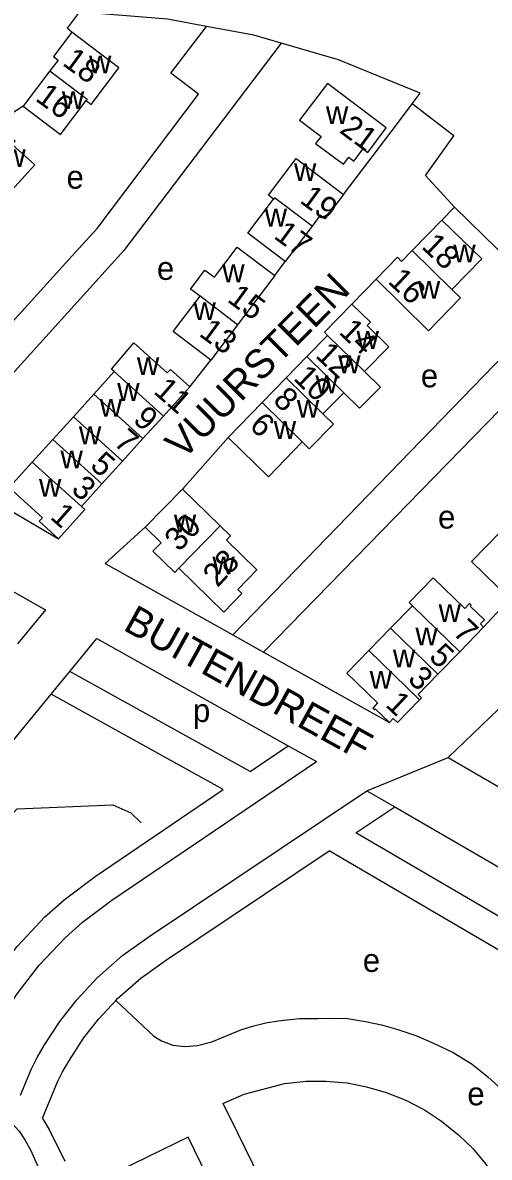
# Model space of a CAD drawing. Extents: x 159441 to 162086, y 388175 to 389787.
# Drawn here: x 161347.7 to 161428.2, y 389289.4 to 389484.9 of the extents above; entities that cross this region are included whole.
import ezdxf

# ---------------------------------------------------------------- set-up
doc = ezdxf.new("R2010")
doc.units = 0
for name, color, linetype in [('BLT_Basislijn', 7, 'Continuous'), ('BLT_Bebouwing', 7, 'Continuous'), ('BLT_Centroide', 7, 'Continuous'), ('BLT_Huisnummer', 7, 'Continuous'), ('BLT_Huisnummer_ tussenligend', 7, 'Continuous'), ('BLT_Onderverdeling_panden', 7, 'Continuous'), ('BLT_Straatnaam', 7, 'Continuous'), ('BLT_Vlakafsluiter', 7, 'Continuous')]:
    doc.layers.add(name, color=color, linetype=linetype)

msp = doc.modelspace()

# ---------------------------------------------------------------- linework, layer by layer
at = {"layer": 'BLT_Basislijn'}
for p, q in [((161356.15, 389483.29), (161355.35, 389483.98)), ((161347.75, 389470.52), (161343.08, 389467.5)), ((161402.99, 389455.31), (161412.3, 389467.53)), ((161422.15, 389453.11), (161417.14, 389458.59)), ((161420, 389450.91), (161422.15, 389453.11)), ((161391.14, 389441.35), (161392.97, 389443.77)), ((161408.63, 389440.71), (161404.43, 389436.41)), ((161383.9, 389379.42), (161439.23, 389436.44)), ((161376.48, 389422.13), (161380.11, 389426.78)), ((161383.09, 389413.41), (161375.23, 389404.54)), ((161368.81, 389397.97), (161361.91, 389391.73)), ((161361.91, 389391.73), (161383.9, 389379.42)), ((161427.19, 389380.73), (161431.71, 389385.62)), ((161421.08, 389358.27), (161444.06, 389380.35)), ((161352.59, 389369.18), (161355.81, 389373.11))]:
    msp.add_line(p, q, dxfattribs=at)
for points in [[(161357.39, 389486.75), (161355.35, 389483.98)], [(161379.36, 389484.27), (161372.66, 389485.51), (161361.32, 389486.43)], [(161334.35, 389420.66), (161357.32, 389445.96), (161360.5, 389449.47), (161378.02, 389472.57), (161373.23, 389476.2), (161379.36, 389484.27)], [(161392.24, 389481.39), (161387.52, 389482.77), (161379.36, 389484.27)], [(161392.24, 389481.39), (161365.12, 389445.63), (161331.26, 389408.25)], [(161414.87, 389470.94), (161416.25, 389472.77), (161402.15, 389478.49), (161392.24, 389481.39)], [(161412.3, 389467.53), (161414.87, 389470.94)], [(161417.14, 389458.59), (161422.02, 389465.43), (161414.87, 389470.94)], [(161439.23, 389436.44), (161422.15, 389453.11)], [(161389.22, 389376.43), (161443.62, 389432.16)], [(161297.62, 389404.04), (161302.19, 389409.6), (161338.34, 389391.17), (161351.6, 389383.74), (161346.77, 389377.86)], [(161331.26, 389408.25), (161344, 389401.76), (161353.86, 389395.98)], [(161383.9, 389379.42), (161389.22, 389376.43)], [(161355.81, 389373.11), (161360.47, 389378.78), (161393.45, 389360.31)], [(161389.22, 389376.43), (161404.55, 389367.85), (161410.92, 389364.29)], [(161386.93, 389355.89), (161355.81, 389373.11)], [(161319.95, 389308.88), (161320.68, 389311.3), (161331.61, 389342.43), (161333.68, 389346.28), (161339.03, 389352.68), (161352.59, 389369.18)], [(161382.28, 389352.75), (161352.59, 389369.18)], [(161386.93, 389355.89), (161393.45, 389360.31)], [(161393.45, 389360.31), (161398.33, 389357.58)], [(161339.24, 389303.76), (161339.4, 389304.13), (161341.55, 389308.92), (161343.9, 389313.22), (161346.73, 389317.54), (161350.53, 389322.46), (161354.99, 389327.2), (161357.99, 389329.87), (161363.07, 389333.69), (161398.33, 389357.58)], [(161421.08, 389358.27), (161443.36, 389345.36)], [(161332.9, 389303.9), (161333.46, 389304.11), (161334.01, 389304.57), (161334.43, 389305.24), (161334.83, 389306.15), (161337.06, 389311.14), (161339.61, 389315.79), (161342.66, 389320.44), (161346.72, 389325.7), (161351.5, 389330.79), (161354.82, 389333.74), (161360.16, 389337.76), (161382.28, 389352.75)], [(161347.32, 389300.09), (161349.17, 389304.61), (161350.19, 389306.55), (161351.46, 389308.73), (161354.07, 389312.79), (161357.02, 389316.52), (161360.52, 389320.29), (161364.92, 389324.19), (161369.65, 389327.54), (161407.03, 389352.54)], [(161407.03, 389352.54), (161411.85, 389349.75)], [(161334.61, 389338.55), (161344.95, 389344.94), (161345.64, 389347), (161345.67, 389348.4), (161346.72, 389349.45), (161363.24, 389350.1), (161366.31, 389348.76), (161368.09, 389347.03)], [(161405.15, 389345.27), (161411.85, 389349.75)], [(161411.85, 389349.75), (161451.41, 389326.83)], [(161437.49, 389326.37), (161405.15, 389345.27)], [(161363.72, 389316.39), (161364.02, 389316.71), (161368.03, 389320.26), (161372.49, 389323.42), (161400.53, 389342.18)], [(161429.8, 389325.08), (161400.53, 389342.18)], [(161351.09, 389296.09), (161353.71, 389302.5), (161354.56, 389304.12), (161355.73, 389306.11), (161358.14, 389309.88), (161360.82, 389313.26), (161363.72, 389316.39)], [(161363.72, 389316.39), (161370.27, 389310.24), (161371.59, 389309.47), (161373.58, 389308.7), (161375.63, 389308.47), (161377.84, 389308.61), (161380.29, 389309.26), (161382.95, 389310.38), (161385.33, 389311.31), (161387.33, 389311.97), (161389.59, 389312.53), (161391.76, 389312.88), (161395.4, 389313.27), (161398.59, 389313.32), (161401.53, 389313.34), (161403.73, 389313.27), (161406.83, 389312.75), (161409.54, 389312.22), (161412.4, 389311.42), (161415.51, 389310.35), (161418.51, 389309.04), (161421.91, 389307.43), (161425.21, 389305.43), (161427.9, 389303.23), (161430.39, 389300.98)], [(161345.46, 389295.54), (161345.74, 389295.3), (161347.05, 389293.86), (161348.06, 389292.39), (161349.03, 389290.66), (161350.35, 389287.69), (161352.98, 389282.25), (161359.9, 389268.04), (161368.55, 389250.2), (161369.85, 389247.56)], [(161351.09, 389296.09), (161351.22, 389295.91)], [(161351.22, 389295.91), (161352.25, 389294.17), (161354.92, 389288.69)], [(161382.75, 389279.37), (161376.24, 389292.82), (161357.36, 389283.67)]]:
    msp.add_lwpolyline(points, dxfattribs=at)
at = {"layer": 'BLT_Bebouwing'}
for p, q in [((161391.14, 389441.35), (161384.72, 389432.87)), ((161396.7, 389427.36), (161400.27, 389431.02)), ((161393.13, 389423.7), (161396.7, 389427.36)), ((161359.92, 389420.89), (161363.45, 389424.79)), ((161388.97, 389419.43), (161393.13, 389423.7)), ((161356.41, 389416.98), (161359.92, 389420.89)), ((161403.06, 389421.14), (161399.47, 389417.49)), ((161388.97, 389419.43), (161383.09, 389413.41)), ((161352.88, 389413.07), (161356.41, 389416.98)), ((161371.94, 389417.13), (161368.41, 389413.23)), ((161349.33, 389409.19), (161352.88, 389413.07)), ((161368.41, 389413.23), (161364.88, 389409.33)), ((161364.88, 389409.33), (161361.35, 389405.43)), ((161361.35, 389405.43), (161357.82, 389401.53))]:
    msp.add_line(p, q, dxfattribs=at)
for points in [[(161356.15, 389483.29), (161352.98, 389479.09), (161353.77, 389478.48), (161352.35, 389476.6)], [(161358.64, 389471.48), (161359.51, 389470.83), (161364.28, 389477.13), (161356.15, 389483.29)], [(161352.35, 389476.6), (161347.75, 389470.52)], [(161395.43, 389468.09), (161399.14, 389465.32), (161398.21, 389464.08), (161402.99, 389460.51), (161403.91, 389461.74), (161404.82, 389461.07), (161406.4, 389463.18), (161407.23, 389462.57), (161410.4, 389466.78), (161400.23, 389474.43), (161395.43, 389468.09)], [(161347.75, 389470.52), (161354.19, 389465.63), (161358.64, 389471.48)], [(161345.75, 389455.97), (161349.75, 389460.41), (161345.87, 389463.91), (161346.4, 389464.5), (161343.08, 389467.5)], [(161390.95, 389454.5), (161390.07, 389455.17), (161394.87, 389461.49), (161402.99, 389455.31)], [(161402.99, 389455.31), (161399.8, 389451.12), (161399.01, 389451.73), (161397.58, 389449.85)], [(161392.97, 389443.77), (161386.5, 389448.63), (161390.95, 389454.5)], [(161397.58, 389449.85), (161392.97, 389443.77)], [(161420, 389450.91), (161414.85, 389445.65)], [(161421.7, 389438.95), (161426.85, 389444.21), (161420, 389450.91)], [(161378.27, 389437.76), (161376.63, 389439.01), (161379.1, 389442.27), (161380.74, 389441.03), (161384.69, 389446.23), (161391.14, 389441.35)], [(161414.85, 389445.65), (161413.02, 389443.78), (161412.3, 389444.48), (161408.63, 389440.71)], [(161408.63, 389440.71), (161417.68, 389431.8), (161423.2, 389437.49), (161421.7, 389438.95)], [(161380.11, 389426.78), (161373.65, 389431.68), (161378.27, 389437.76)], [(161404.43, 389436.41), (161399.71, 389431.57), (161400.27, 389431.02)], [(161406.64, 389424.79), (161410.83, 389429.06), (161407.09, 389432.71), (161407.65, 389433.28), (161404.43, 389436.41)], [(161384.72, 389432.87), (161380.11, 389426.78)], [(161363.45, 389424.79), (161362.98, 389425.23), (161366.87, 389429.74), (161372.61, 389424.55), (161373.15, 389425.15), (161376.48, 389422.13)], [(161406.64, 389424.79), (161409.38, 389422.12), (161405.8, 389418.46), (161403.06, 389421.14)], [(161376.48, 389422.13), (161371.94, 389417.13)], [(161395.9, 389412.65), (161397.11, 389411.47), (161401.27, 389415.75), (161399.47, 389417.49)], [(161383.09, 389413.41), (161390.06, 389406.64), (161395.9, 389412.65)], [(161353.86, 389395.98), (161350.53, 389398.99), (161351.07, 389399.58), (161345.34, 389404.78), (161349.33, 389409.19)], [(161375.23, 389404.54), (161368.81, 389397.97)], [(161381.76, 389398.18), (161375.23, 389404.54)], [(161357.82, 389401.53), (161358.41, 389401.01), (161353.86, 389395.98)], [(161368.81, 389397.97), (161371.56, 389395.29), (161370.14, 389393.84), (161373.91, 389390.16), (161374.63, 389390.89)], [(161374.63, 389390.89), (161382.35, 389383.34), (161385.47, 389386.53), (161384.78, 389387.2), (161388.09, 389390.59), (161382.82, 389395.73), (161383.53, 389396.45), (161381.76, 389398.18)], [(161430.26, 389397.32), (161425.12, 389392.05), (161431.71, 389385.62)], [(161427.19, 389380.73), (161426.63, 389381.29), (161427.32, 389381.99), (161424.87, 389384.37), (161425.02, 389384.53), (161424.77, 389384.82), (161423.93, 389383.95), (161418.49, 389389.26), (161414.33, 389385), (161414.91, 389384.43)], [(161414.91, 389384.43), (161411.14, 389380.57)], [(161411.14, 389380.57), (161407.37, 389376.7)], [(161423.06, 389376.49), (161427.19, 389380.73)], [(161407.37, 389376.7), (161403.6, 389372.83), (161408.9, 389367.67), (161408.06, 389366.8), (161408.36, 389366.51), (161408.5, 389366.65), (161410.92, 389364.29)], [(161419.29, 389372.62), (161423.06, 389376.49)], [(161416.1, 389368.19), (161416.46, 389368.57), (161415.88, 389369.13), (161419.29, 389372.62)], [(161412.3, 389364.3), (161416.1, 389368.19)], [(161410.92, 389364.29), (161411.6, 389364.98), (161412.3, 389364.3)], [(161382.22, 389298.65), (161385.9, 389300.24), (161392.81, 389302.09), (161396.59, 389302.49), (161399.97, 389302.49), (161403.62, 389302.18), (161406.98, 389301.53), (161410.36, 389300.54), (161413.77, 389299.23), (161417.01, 389297.53), (161419.89, 389295.62), (161422.9, 389293.21), (161425.31, 389290.9), (161427.55, 389288.2), (161429.58, 389285.25), (161433.77, 389277.04)], [(161382.22, 389298.65), (161383.39, 389296.28)], [(161383.39, 389296.28), (161389.95, 389282.88), (161382.75, 389279.37)]]:
    msp.add_lwpolyline(points, dxfattribs=at)
at = {"layer": 'BLT_Onderverdeling_panden'}
for p, q in [((161414.85, 389445.65), (161421.7, 389438.95)), ((161384.72, 389432.87), (161378.27, 389437.76)), ((161406.64, 389424.79), (161400.27, 389431.02)), ((161396.7, 389427.36), (161403.06, 389421.14)), ((161363.45, 389424.79), (161371.94, 389417.13)), ((161399.47, 389417.49), (161393.13, 389423.7)), ((161368.41, 389413.23), (161359.92, 389420.89)), ((161388.97, 389419.43), (161395.9, 389412.65)), ((161356.41, 389416.98), (161364.88, 389409.33)), ((161361.35, 389405.43), (161352.88, 389413.07)), ((161349.33, 389409.19), (161357.82, 389401.53))]:
    msp.add_line(p, q, dxfattribs=at)
for points in [[(161352.35, 389476.6), (161358.82, 389471.72), (161358.64, 389471.48)], [(161397.58, 389449.85), (161391.13, 389454.74), (161390.95, 389454.5)], [(161374.63, 389390.89), (161381.76, 389398.18)], [(161414.91, 389384.43), (161423.06, 389376.49)], [(161411.14, 389380.57), (161419.29, 389372.62)], [(161407.37, 389376.7), (161416.1, 389368.19)]]:
    msp.add_lwpolyline(points, dxfattribs=at)
at = {"layer": 'BLT_Vlakafsluiter'}
msp.add_line((161407.03, 389352.54), (161421.08, 389358.27), dxfattribs=at)

# ---------------------------------------------------------------- texts
at = {"layer": 'BLT_Centroide'}
for s, p in [('w', (161359.11, 389476.18)), ('w', (161354.43, 389470.03)), ('w', (161399.98, 389467.44)), ('w', (161344.34, 389460.04)), ('e', (161355.24, 389456.31)), ('w', (161394.47, 389457.63)), ('w', (161389.41, 389449.79)), ('w', (161421.95, 389443.6)), ('e', (161370.83, 389440.59)), ('w', (161382.09, 389440.17)), ('w', (161415.83, 389437.33)), ('w', (161377.13, 389433.66)), ('w', (161405.26, 389428.69)), ('w', (161367.37, 389424.18)), ('w', (161402.09, 389424.51)), ('w', (161398.18, 389421.04)), ('e', (161416.36, 389422.07)), ('w', (161363.98, 389419.73)), ('w', (161360.96, 389416.99)), ('w', (161394.97, 389416.82)), ('w', (161390.98, 389413.19)), ('w', (161357.37, 389412.27)), ('w', (161354.19, 389408.09)), ('w', (161350.48, 389403.22)), ('e', (161419.32, 389397.73)), ('w', (161373.74, 389397.07)), ('w', (161380.4, 389389.82)), ('w', (161419.41, 389381.62)), ('w', (161415.41, 389377.6)), ('w', (161411.53, 389373.79)), ('w', (161407.53, 389370.12)), ('p', (161377.05, 389364.39)), ('e', (161406.35, 389321.32)), ('e', (161424.38, 389298.33))]:
    msp.add_text(s, height=4, dxfattribs=at).set_placement(p)
at = {"layer": 'BLT_Huisnummer'}
for s, rotation, p in [('18', 323.8661, (161354.35, 389477.72)), ('16', 323.7653, (161349.69, 389471.61)), ('21', 323.6677, (161402.13, 389466.11)), ('19', 323.8566, (161395.28, 389454.03)), ('17', 323.7966, (161390.8, 389447.88)), ('18', 316.7235, (161416.3, 389446.17)), ('16', 316.7085, (161410.5, 389440.17)), ('13', 323.7966, (161377.91, 389431.06)), ('14', 316.6674, (161402.05, 389431.43)), ('10', 315.8103, (161394.2, 389423.5)), ('9', 318.84, (161366.52, 389416.23)), ('6', 316.7953, (161386.59, 389415.22)), ('5', 318.84, (161359.12, 389408.33)), ('1', 318.84, (161352.23, 389399.55)), ('30', 46.5638, (161374.64, 389393.59)), ('28', 46.7737, (161381.27, 389387.46)), ('7', 316.7296, (161421.69, 389379.63)), ('5', 316.7296, (161417.56, 389375.43)), ('1', 316.7737, (161410.09, 389367.2))]:
    msp.add_text(s, height=4, rotation=rotation, dxfattribs=at).set_placement(p)
at = {"layer": 'BLT_Huisnummer_ tussenligend'}
for s, rotation, p in [('15', 323.8566, (161382.77, 389436.96)), ('12', 316.7953, (161397.98, 389427.4)), ('11', 318.84, (161370.07, 389421.17)), ('8', 316.8122, (161390.67, 389419.62)), ('7', 318.84, (161363.18, 389412.31)), ('3', 319.947, (161355.85, 389404.19)), ('3', 316.8827, (161413.9, 389371.57))]:
    msp.add_text(s, height=4, rotation=rotation, dxfattribs=at).set_placement(p)
at = {"layer": 'BLT_Straatnaam'}
for s, rotation, p in [('VUURSTEEN', 45.0628, (161375.33, 389409.42)), ('BUITENDREEF', 331.0628, (161364.81, 389380.36))]:
    msp.add_text(s, height=5, rotation=rotation, dxfattribs=at).set_placement(p)

doc.saveas('drawing.dxf')
